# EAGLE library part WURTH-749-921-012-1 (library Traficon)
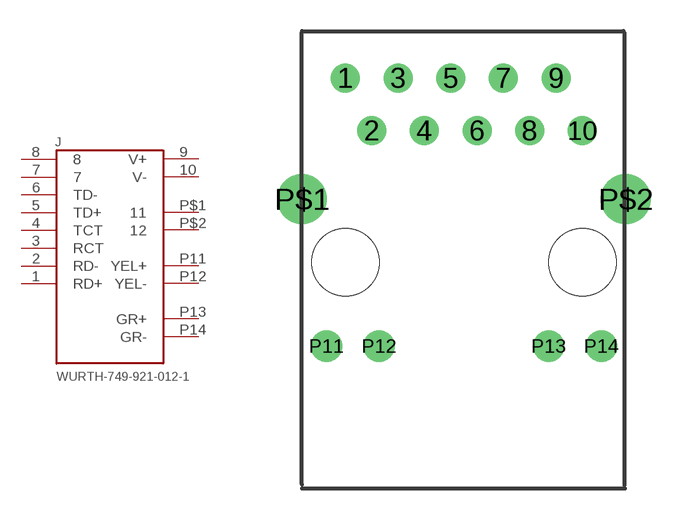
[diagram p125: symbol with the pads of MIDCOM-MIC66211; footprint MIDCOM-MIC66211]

Designator prefix J

## WURTH-749-921-012-1  [MIDCOM-MIC66211]
1  RD+  pas
2  RD-  pas
3  RCT  pas
4  TCT  pas
5  TD+  pas
6  TD-  pas
7  7  pas
8  8  pas
9  V+  pas
10  V-  pas
P11  YEL+
P12  YEL-
P13  GR+
P14  GR-
P$1  11  pas
P$2  12  pas

## Footprint MIDCOM-MIC66211 (pad centres in mm)
drill 0.889 round: 1 -5.715,8.89; 2 -4.445,6.35; 3 -3.175,8.89; 4 -1.905,6.35; 5 -0.635,8.89; 6 0.635,6.35; 7 1.905,8.89; 8 3.175,6.35; 9 4.445,8.89; 10 5.715,6.35
drill 1 round: P11 -6.63,-4.06; P12 -4.09,-4.06; P13 4.09,-4.06; P14 6.63,-4.06
drill 1.6 round: P$1 -7.81,3.05; P$2 7.81,3.05
hole 3.251 at -5.715,0
hole 3.251 at 5.715,0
